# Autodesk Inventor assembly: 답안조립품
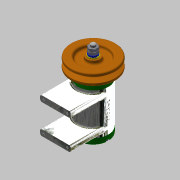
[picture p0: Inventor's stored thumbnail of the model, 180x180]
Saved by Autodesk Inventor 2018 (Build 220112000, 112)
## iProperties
Created: 2020-07
Part Number: 답안조립품
Material: 일반
Document SubType Name: Assembly
Designer: home
Author: home
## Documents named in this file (15)
- C:\Users\home\Desktop\700706V1027\답안조립품.iam
- C:\Users\home\Desktop\700706V1027\본체.ipt
- C:\Users\home\Desktop\700706V1027\베어링 6002.ipt
- C:\Users\home\Desktop\700706V1027\축.ipt
- C:\Users\home\Desktop\700706V1027\앞커버.ipt
- C:\Users\home\Desktop\700706V1027\뒤커버.ipt
- C:\Users\home\Desktop\700706V1027\오일 실 15 25 7.ipt
- C:\Users\home\Desktop\700706V1027\키 3x3x12.ipt
- C:\Users\home\Desktop\700706V1027\볼트 M4x12.ipt
- C:\Users\home\Desktop\700706V1027\V벨트풀리.ipt
- C:\Users\home\Desktop\700706V1027\스프링와셔 8.ipt
- C:\Users\home\Desktop\700706V1027\와셔 8x17.ipt
- C:\Users\home\Desktop\700706V1027\너트 M8.ipt
- C:\Users\home\Desktop\700706V1027\와셔 6x11.5.ipt
- C:\Users\home\Desktop\700706V1027\볼트 M6x8.ipt
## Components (1 placed, 1 different names)
1. V벨트풀리:1
